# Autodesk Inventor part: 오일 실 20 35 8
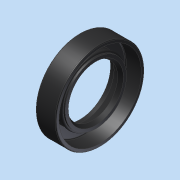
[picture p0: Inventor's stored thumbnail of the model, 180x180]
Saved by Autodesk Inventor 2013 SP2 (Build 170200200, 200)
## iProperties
Created: 2026-01
Part Number: 오일 실 20 35 8
Material: Generic
Document SubType Name: Modeling
Designer: a
Density: 1 g/cm^3
Author: a
변환 표준: STEP AP214IS
전처리기: Build: 200, Release: 2013 SP2 Update 6 - Date: Thu 07/17/2014
전송 단위: 밀리미터
불확실성: 0.01
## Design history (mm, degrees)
node "오일 실 20 35 81"
body "Solid1"
node "기준1"
